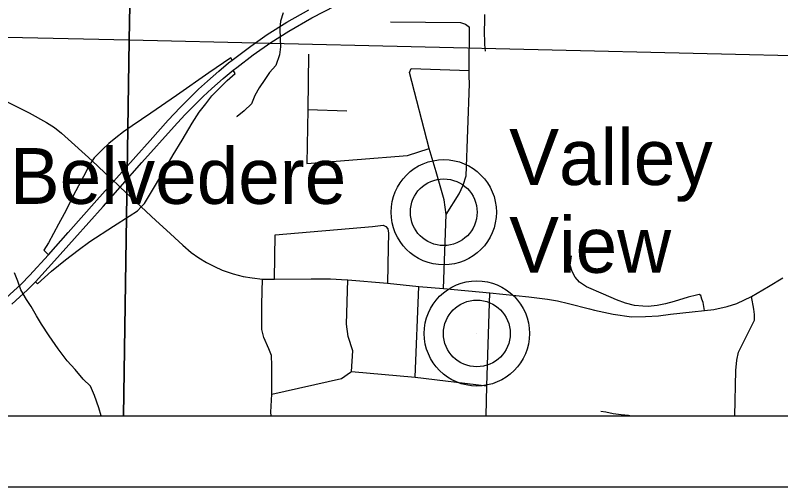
# Model space of a CAD drawing. Extents: x -19 to 40.8, y -1.8 to 26.1.
# Drawn here: x 3.175 to 4.257, y 14 to 14.667 of the extents above; entities that cross this region are included whole.
import ezdxf

# ---------------------------------------------------------------- set-up
doc = ezdxf.new("R2010")
doc.units = 0
for name, color, linetype in [('Default', 7, 'Continuous'), ('GM_X_Corporation', 7, 'Continuous'), ('GM_X_Corporation_Text', 7, 'Continuous'), ('GM_X_County_Road', 7, 'Continuous'), ('GM_X_Major_River', 7, 'Continuous'), ('GM_X_Section', 7, 'Continuous'), ('GM_X_State_Route', 7, 'Continuous'), ('GM_X_Township_Road', 7, 'Continuous'), ('GM_X_Unincorporated', 7, 'Continuous'), ('RW_P_Text', 7, 'Continuous'), ('SH_Data', 7, 'Continuous')]:
    doc.layers.add(name, color=color, linetype=linetype)

msp = doc.modelspace()

# ---------------------------------------------------------------- linework, layer by layer
at = {"layer": 'Default'}
for points in [[(2.3441, 14.1), (3.3277, 14.1), (3.3355, 14.6314), (2.3446, 14.653)], [(3.3277, 14.1), (4.3224, 14.1), (4.3324, 14.6079), (3.3355, 14.6314)]]:
    msp.add_lwpolyline(points, close=True, dxfattribs=at)
at = {"layer": 'GM_X_Corporation'}
for points in [[(3.1327, 14.5595), (3.1497, 14.5509), (3.1941, 14.5287), (3.2186, 14.5153), (3.2302, 14.5078), (3.2401, 14.5), (3.259, 14.4832), (3.2832, 14.4611), (3.3009, 14.4443), (3.314, 14.4321), (3.3181, 14.4282)], [(3.3181, 14.4282), (3.323, 14.4237), (3.3525, 14.3959), (3.3735, 14.3764), (3.3882, 14.3627), (3.4114, 14.3414), (3.4234, 14.3314), (3.4342, 14.3238), (3.4449, 14.3173), (3.4562, 14.3113), (3.4672, 14.3064), (3.4825, 14.3011), (3.4967, 14.2975), (3.5095, 14.2954), (3.5242, 14.2936), (3.541, 14.2936), (3.5929, 14.294), (3.6201, 14.2938), (3.6439, 14.2927)], [(3.6439, 14.2927), (3.6449, 14.2926), (3.7006, 14.2877), (3.7449, 14.2833), (3.7798, 14.2801), (3.8453, 14.2741), (3.9004, 14.2683), (3.9268, 14.2654), (3.941, 14.2628), (3.9565, 14.2592), (3.9864, 14.2515)], [(3.9864, 14.2515), (3.9932, 14.2497), (4.0196, 14.2439), (4.0456, 14.2404), (4.0655, 14.2407), (4.0839, 14.2418), (4.1008, 14.2438), (4.1317, 14.2471), (4.149, 14.2492), (4.1621, 14.2508), (4.181, 14.2547), (4.1946, 14.2591), (4.2154, 14.269), (4.2392, 14.2829), (4.2596, 14.2953)]]:
    msp.add_lwpolyline(points, dxfattribs=at)
at = {"layer": 'GM_X_County_Road'}
for points in [[(3.4812, 14.6033), (3.4792, 14.6064), (3.4483, 14.5851), (3.4026, 14.5533), (3.3663, 14.5284), (3.3401, 14.5106), (3.3274, 14.5017), (3.3168, 14.4935), (3.3071, 14.4854), (3.2978, 14.4767), (3.2862, 14.465), (3.2832, 14.4611)], [(3.3525, 14.3959), (3.3575, 14.4007), (3.37, 14.4219), (3.3805, 14.4393), (3.398, 14.4692), (3.4106, 14.4903), (3.4248, 14.5142), (3.4347, 14.5295), (3.4438, 14.5416), (3.4527, 14.5526), (3.4618, 14.5623), (3.474, 14.5743), (3.4857, 14.5845), (3.4827, 14.5889)], [(3.2832, 14.4611), (3.2797, 14.4554), (3.271, 14.4389), (3.2602, 14.4182), (3.2436, 14.3861), (3.2357, 14.3711), (3.2216, 14.3447), (3.2151, 14.3345), (3.2215, 14.3281)], [(3.2033, 14.2899), (3.2061, 14.287), (3.226, 14.3048), (3.2455, 14.3209), (3.2636, 14.3347), (3.2802, 14.3467), (3.3135, 14.3685), (3.3355, 14.3828), (3.3474, 14.3901), (3.3525, 14.3959)]]:
    msp.add_lwpolyline(points, dxfattribs=at)
at = {"layer": 'GM_X_Major_River'}
for p, q in [((3.7803, 14.3882), (3.7803, 14.3882)), ((3.8271, 14.2167), (3.8271, 14.2167))]:
    msp.add_line(p, q, dxfattribs=at)
at = {"layer": 'GM_X_Section'}
for points in [[(3.5531, 14.6701), (3.5495, 14.6583), (3.5484, 14.6476), (3.5493, 14.634), (3.5494, 14.6222), (3.5483, 14.6108), (3.5428, 14.5955), (3.5341, 14.5856), (3.5274, 14.576), (3.5195, 14.5642), (3.5131, 14.5535), (3.5087, 14.5413), (3.4981, 14.5317), (3.4883, 14.5237), (3.4875, 14.5233)], [(3.8381, 14.6678), (3.8378, 14.6568), (3.8375, 14.6462), (3.8377, 14.6253), (3.8389, 14.6162)], [(3.2959, 14.1), (3.2928, 14.1113), (3.2865, 14.1291), (3.2811, 14.142), (3.2704, 14.1522), (3.2592, 14.1658), (3.2481, 14.1782), (3.2351, 14.1948), (3.2224, 14.2133), (3.2116, 14.23), (3.2046, 14.2417), (3.1973, 14.2549), (3.1904, 14.2648), (3.1827, 14.2784), (3.1784, 14.2909), (3.1734, 14.3026)], [(4.0435, 14.1), (4.0416, 14.1006), (4.031, 14.1017), (4.0196, 14.1031), (4.0093, 14.1053), (4.0025, 14.1064)]]:
    msp.add_lwpolyline(points, dxfattribs=at)
at = {"layer": 'GM_X_State_Route'}
for p, q in [((3.7344, 14.5914), (3.8161, 14.5886)), ((3.588, 14.5335), (3.6434, 14.5318)), ((3.7398, 14.1548), (3.7449, 14.2833))]:
    msp.add_line(p, q, dxfattribs=at)
msp.add_lwpolyline([(2.1, 15.8991), (2.1, 14.1), (4.3215, 14.1), (4.3262, 14.3024), (4.3261, 14.4335), (4.3369, 14.8581), (4.3371, 14.8653), (4.3373, 14.8703), (4.3441, 15.1043), (4.3494, 15.3211), (4.3628, 15.868), (3.9893, 15.872), (3.7032, 15.8784), (3.0926, 15.8861), (2.1833, 15.8974)], close=True, dxfattribs=at)
for points in [[(3.7052, 14.6577), (3.8039, 14.6565), (3.811, 14.6541), (3.8165, 14.6499)], [(3.8164, 14.5807), (3.8161, 14.5886), (3.8165, 14.6499)], [(3.5892, 14.6118), (3.588, 14.5335), (3.5867, 14.457), (3.7292, 14.4684), (3.7599, 14.4781)], [(3.7836, 14.3851), (3.781, 14.4057), (3.7695, 14.4455), (3.7599, 14.4781), (3.732, 14.5856), (3.7344, 14.5914)], [(3.7798, 14.2801), (3.7836, 14.3851), (3.8019, 14.4143), (3.8079, 14.4266), (3.8119, 14.4395), (3.8169, 14.5698), (3.8164, 14.5807)], [(3.541, 14.2936), (3.542, 14.356), (3.6796, 14.3679), (3.6949, 14.3701), (3.6986, 14.3681), (3.7015, 14.3647), (3.7023, 14.3585), (3.7017, 14.3384), (3.7006, 14.2877)], [(4.149, 14.2492), (4.1468, 14.2603), (4.145, 14.2652), (4.1435, 14.2702), (4.1413, 14.2717), (4.1376, 14.2708), (4.126, 14.268), (4.1061, 14.2617), (4.0936, 14.2584), (4.0818, 14.2562), (4.0691, 14.2549), (4.0619, 14.2553), (4.0501, 14.2564), (4.0372, 14.2597), (4.0247, 14.2641), (4.0063, 14.2722), (3.9823, 14.2827), (3.9722, 14.2894), (3.9659, 14.2964), (3.9619, 14.3043), (3.9591, 14.3135), (3.961, 14.3264)], [(3.5363, 14.1), (3.5358, 14.1055), (3.5372, 14.131), (3.5372, 14.1715), (3.537, 14.1854), (3.5329, 14.195), (3.526, 14.2111), (3.5233, 14.2221), (3.5233, 14.2581), (3.5242, 14.2936)], [(3.6501, 14.1631), (3.6519, 14.1919), (3.6452, 14.2123), (3.6428, 14.2299), (3.6449, 14.2926)], [(3.8402, 14.1), (3.8413, 14.1424), (3.8453, 14.2741)], [(4.1916, 14.1), (4.1932, 14.1644), (4.1947, 14.179), (4.197, 14.1903), (4.2194, 14.2357), (4.2198, 14.2435), (4.2185, 14.2512), (4.2154, 14.269)], [(3.6486, 14.162), (3.6501, 14.1631), (3.7398, 14.1548), (3.8413, 14.1424)], [(3.5372, 14.131), (3.6359, 14.1531), (3.6486, 14.162)]]:
    msp.add_lwpolyline(points, dxfattribs=at)
at = {"layer": 'GM_X_Township_Road'}
for points in [[(3.1614, 14.2665), (3.1834, 14.2869), (3.1947, 14.2985), (3.2215, 14.3281), (3.2496, 14.3597), (3.2899, 14.405), (3.314, 14.4321), (3.3451, 14.4671), (3.3652, 14.4898), (3.3908, 14.5183), (3.4076, 14.5363), (3.4191, 14.5478), (3.4337, 14.5622), (3.4462, 14.5736), (3.4622, 14.5877), (3.4762, 14.5993), (3.4812, 14.6033), (3.5077, 14.6232), (3.5309, 14.6394), (3.5585, 14.6569), (3.5894, 14.6745)], [(3.17, 14.2579), (3.192, 14.2783), (3.2033, 14.2899), (3.2301, 14.3195), (3.2582, 14.3512), (3.2987, 14.3965), (3.323, 14.4237), (3.3537, 14.4585), (3.3993, 14.5096), (3.4141, 14.5259), (3.4256, 14.5373), (3.4402, 14.5518), (3.4527, 14.5632), (3.4687, 14.5772), (3.4827, 14.5889), (3.4877, 14.5929), (3.5109, 14.6106), (3.5358, 14.6282), (3.5611, 14.6444), (3.5938, 14.6633), (3.6276, 14.6807)]]:
    msp.add_lwpolyline(points, dxfattribs=at)
at = {"layer": 'GM_X_Unincorporated'}
for centre, radius in [((3.7803, 14.3882), 0.0744), ((3.7803, 14.3882), 0.0472), ((3.8271, 14.2167), 0.0744), ((3.8271, 14.2167), 0.0472)]:
    msp.add_circle(centre, radius, dxfattribs=at)
at = {"layer": 'RW_P_Text'}
for points in [[(2.3634, 15.8992), (3.3595, 15.883), (3.3355, 14.6314), (2.3446, 14.653)], [(3.3595, 15.883), (4.3635, 15.8676), (4.3391, 14.8802), (4.3324, 14.6079), (3.3355, 14.6314)]]:
    msp.add_lwpolyline(points, close=True, dxfattribs=at)
at = {"layer": 'SH_Data'}
for p, q in [((2.1, 14.1), (8.9, 14.1)), ((2, 14), (9, 14))]:
    msp.add_line(p, q, dxfattribs=at)

# ---------------------------------------------------------------- texts
at = {"layer": 'GM_X_Corporation_Text'}
for s, p in [('Valley', (3.8728, 14.4267)), ('Belvedere', (3.1669, 14.4)), ('View', (3.8728, 14.3025))]:
    msp.add_text(s, height=0.07898, rotation=0, dxfattribs=at).set_placement(p)

doc.saveas('drawing.dxf')
